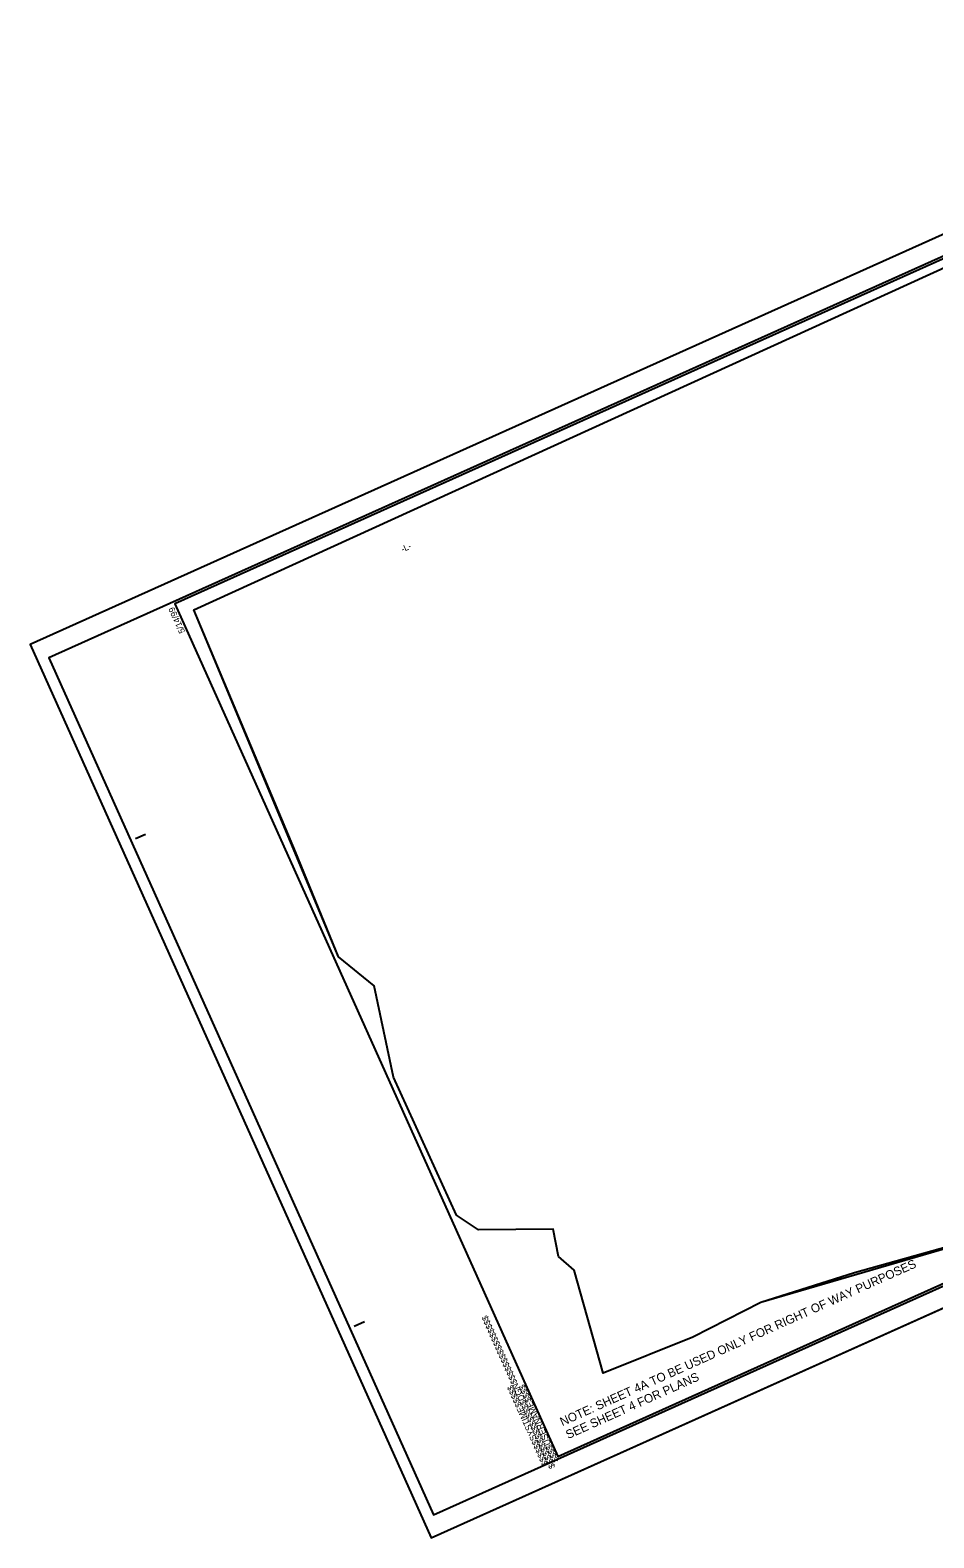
# Model space of a CAD drawing. Extents: x 553939 to 555925, y 502653 to 504347.
# Drawn here: x 553939 to 554954, y 502653 to 504347 of the extents above; entities that cross this region are included whole.
import ezdxf

# ---------------------------------------------------------------- set-up
doc = ezdxf.new("R2010")
doc.units = 0
for name, color, linetype in [('Prop Horizontal Alignment Curve and Spiral Data', 7, 'Continuous'), ('Prop Horizontal Alignment Direction Label', 7, 'Continuous'), ('Prop Horizontal Alignment Station Label', 7, 'Continuous'), ('Prop SS Cut Line', 7, 'Continuous'), ('Prop SS Fill Line', 7, 'Continuous'), ('Scratch_Level_9', 7, 'Continuous'), ('Sheet Clip Boundary CELL', 7, 'Continuous')]:
    doc.layers.add(name, color=color, linetype=linetype)

msp = doc.modelspace()

# ---------------------------------------------------------------- linework, layer by layer
at = {"layer": 'Prop Horizontal Alignment Direction Label'}
msp.add_lwpolyline([(555474.9, 504346.6), (553938.6, 503656.8), (554389.2, 502653.3), (555925.5, 503343.1)], close=True, dxfattribs=at)
at = {"layer": 'Prop SS Cut Line'}
for p, q in [((554102.1, 503702.8), (554102.1, 503702.8)), ((554056.9, 503438.6), (554068.3, 503443.7)), ((554302.7, 502891.2), (554314.1, 502896.4))]:
    msp.add_line(p, q, dxfattribs=at)
msp.add_lwpolyline([(555469.6, 504316.8), (554101.2, 503702.4), (554531.3, 502744.5), (555899.7, 503359)], close=True, dxfattribs=at)
at = {"layer": 'Prop SS Fill Line'}
msp.add_lwpolyline([(555480, 504324.3), (553959.7, 503641.6), (554391.9, 502679.1), (555912.2, 503361.8)], close=True, dxfattribs=at)
at = {"layer": 'Scratch_Level_9'}
for p, q in [((555474.9, 504346.6), (553938.6, 503656.8)), ((553938.6, 503656.8), (554389.2, 502653.3)), ((554389.2, 502653.3), (555925.5, 503343.1))]:
    msp.add_line(p, q, dxfattribs=at)
at = {"layer": 'Sheet Clip Boundary CELL'}
msp.add_lwpolyline([(555094.7, 503015.3), (554864.6, 502951), (554759.3, 502917.8), (554683, 502878.6), (554582.3, 502838.3), (554549.8, 502954), (554532.1, 502969.2), (554526, 503000), (554442.4, 502999.3), (554417.7, 503015.9), (554346.9, 503170.6), (554325.2, 503273.4), (554285.2, 503305.8), (554236.8, 503423.9), (554122.4, 503695.7), (555128.4, 504154.2)], dxfattribs=at)
msp.add_lwpolyline([(555608.3, 503927.6), (555814.9, 503478.7), (555868.6, 503357.4), (555700, 503280.3), (555094.7, 503015.3), (554759.3, 502917.8), (554683, 502878.6), (554582.3, 502838.3), (554549.8, 502954), (554532.1, 502969.2), (554526, 503000), (554442.4, 502999.3), (554417.7, 503015.9), (554346.9, 503170.6), (554325.2, 503273.4), (554285.2, 503305.8), (554122.4, 503695.7), (555128.4, 504154.2), (555095.7, 504120), (555113.6, 504088.1), (555364, 504064.8), (555538.1, 504148), (555542.5, 504077.4), (555561.4, 504001)], close=True, dxfattribs=at)

# ---------------------------------------------------------------- texts
at = {"layer": 'Prop Horizontal Alignment Curve and Spiral Data'}
for s, p in [('NOTE: SHEET 4A TO BE USED ONLY FOR RIGHT OF WAY PURPOSES', (554536.5, 502778.6)), ('SEE SHEET 4 FOR PLANS', (554543, 502764.1))]:
    msp.add_text(s, height=9.8, rotation=24.1816, dxfattribs=at).set_placement(p)
at = {"layer": 'Prop Horizontal Alignment Station Label'}
msp.add_text('-L-', height=7, rotation=24.1816, dxfattribs=at).set_placement((554357.1, 503760.1))
at = {"layer": 'Prop SS Cut Line'}
for s, p in [('5/14/99', (554112.9, 503671)), ('$$$$$$$$$$$$$$$$DGN$$$$$$$$$$$$$$$$', (554528.7, 502732.9)), ('$$$$$$SYSTIME$$$$$', (554520.8, 502735.7)), ('$$$$USERNAME$$$$', (554532.5, 502739.9))]:
    msp.add_text(s, height=7, rotation=114.1816, dxfattribs=at).set_placement(p)

doc.saveas('drawing.dxf')
